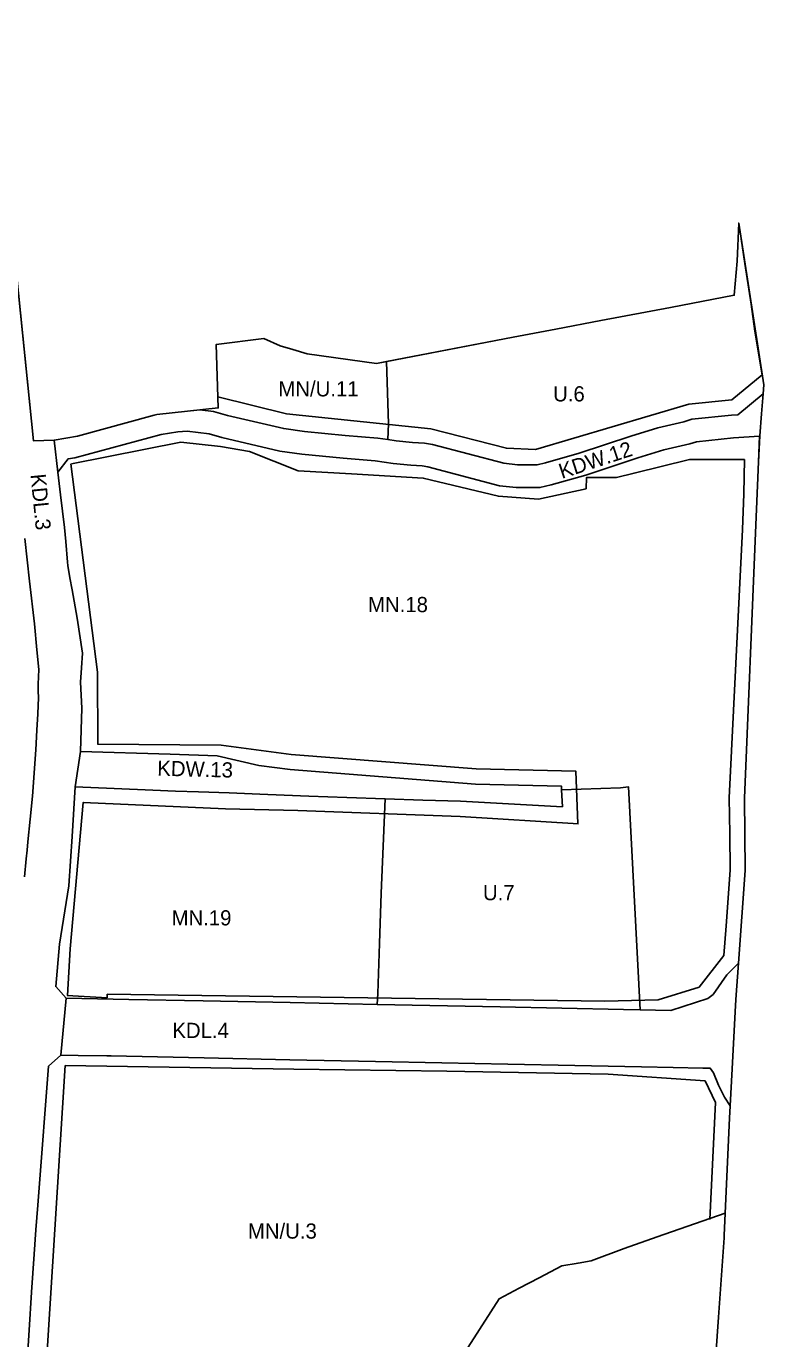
# Model space of a CAD drawing. Extents: x 7423274 to 7424514, y 5542390 to 5544261.
# Drawn here: x 7424240.7 to 7424434.8, y 5543020.6 to 5543366 of the extents above; entities that cross this region are included whole.
import ezdxf

# ---------------------------------------------------------------- set-up
doc = ezdxf.new("R2010")
doc.units = 0
for name, color, linetype in [('granica obszaru objętego planem', 7, 'Continuous'), ('LIN_Granica Planu', 7, 'Continuous'), ('linie rozgraniczające tereny o różnym przeznaczeniu lub różnych zasadach zagospodarowania', 7, 'Continuous'), ('nieprzekraczalna linia zabudowy', 7, 'Continuous'), ('oznaczenia terenów', 7, 'Continuous')]:
    doc.layers.add(name, color=color, linetype=linetype)

msp = doc.modelspace()

# ---------------------------------------------------------------- linework, layer by layer
at = {"layer": 'granica obszaru objętego planem'}
for p, q in [((7424228.51, 5543394.73), (7424242.62, 5543256.86)), ((7424427.77, 5543304.14), (7424428.18, 5543314.14)), ((7424428.18, 5543314.14), (7424434.77, 5543271.57)), ((7424391.88, 5543288.5), (7424410.21, 5543291.99)), ((7424380.04, 5543286.24), (7424391.88, 5543288.5)), ((7424303.2, 5543283.79), (7424307.53, 5543281.87)), ((7424332.88, 5543277.25), (7424368.81, 5543284.1)), ((7424368.81, 5543284.1), (7424380.04, 5543286.24)), ((7424307.53, 5543281.87), (7424310.86, 5543280.86)), ((7424310.86, 5543280.86), (7424314.62, 5543279.75)), ((7424314.62, 5543279.75), (7424332.88, 5543277.25)), ((7424254.14, 5543258.07), (7424274.35, 5543263.58)), ((7424274.35, 5543263.58), (7424275.03, 5543263.77)), ((7424275.03, 5543263.77), (7424291.22, 5543265.54)), ((7424434.16, 5543263.98), (7424433.7, 5543258.21)), ((7424242.62, 5543256.86), (7424248.04, 5543257.08)), ((7424248.04, 5543257.08), (7424254.14, 5543258.07)), ((7424433.7, 5543258.21), (7424433.42, 5543251.38)), ((7424433.42, 5543251.38), (7424432.63, 5543232.65)), ((7424432.63, 5543232.65), (7424429.7, 5543162.87)), ((7424429.7, 5543162.87), (7424429.92, 5543143.78)), ((7424427.46, 5543109.89), (7424427.29, 5543106.64)), ((7424427.29, 5543106.64), (7424426.47, 5543091.66)), ((7424426.47, 5543091.66), (7424425.77, 5543078.62))]:
    msp.add_line(p, q, dxfattribs=at)
for points in [[(7424410.21, 5543291.99), (7424426.99, 5543295.19), (7424427.77, 5543304.14)], [(7424291.22, 5543265.54), (7424290.65, 5543282.2), (7424303.2, 5543283.79)], [(7424434.77, 5543271.57), (7424434.59, 5543269.27), (7424434.16, 5543263.98)], [(7424429.92, 5543143.78), (7424428.16, 5543119.46), (7424427.46, 5543109.89)], [(7424425.77, 5543078.62), (7424424.34, 5543047.76), (7424424.32, 5543047.16)], [(7424424.32, 5543047.16), (7424422.87, 5543026.31), (7424417.89, 5542954.87)]]:
    msp.add_lwpolyline(points, dxfattribs=at)
at = {"layer": 'LIN_Granica Planu'}
for p, q in [((7424242.62, 5543256.86), (7424228.51, 5543394.73)), ((7424428.18, 5543314.14), (7424427.77, 5543304.14)), ((7424434.77, 5543271.57), (7424428.18, 5543314.14)), ((7424410.21, 5543291.99), (7424391.88, 5543288.5)), ((7424391.88, 5543288.5), (7424380.04, 5543286.24)), ((7424307.53, 5543281.87), (7424303.2, 5543283.79)), ((7424368.81, 5543284.1), (7424332.88, 5543277.25)), ((7424380.04, 5543286.24), (7424368.81, 5543284.1)), ((7424310.86, 5543280.86), (7424307.53, 5543281.87)), ((7424314.62, 5543279.75), (7424310.86, 5543280.86)), ((7424332.88, 5543277.25), (7424314.62, 5543279.75)), ((7424274.35, 5543263.58), (7424254.14, 5543258.07)), ((7424275.03, 5543263.77), (7424274.35, 5543263.58)), ((7424291.22, 5543265.54), (7424275.03, 5543263.77)), ((7424433.7, 5543258.21), (7424434.16, 5543263.98)), ((7424248.04, 5543257.08), (7424242.62, 5543256.86)), ((7424254.14, 5543258.07), (7424248.04, 5543257.08)), ((7424433.42, 5543251.38), (7424433.7, 5543258.21)), ((7424432.63, 5543232.65), (7424433.42, 5543251.38)), ((7424429.7, 5543162.87), (7424432.63, 5543232.65)), ((7424429.92, 5543143.78), (7424429.7, 5543162.87)), ((7424427.29, 5543106.64), (7424427.46, 5543109.89)), ((7424426.47, 5543091.66), (7424427.29, 5543106.64)), ((7424425.77, 5543078.62), (7424426.47, 5543091.66))]:
    msp.add_line(p, q, dxfattribs=at)
for points in [[(7424427.77, 5543304.14), (7424426.99, 5543295.19), (7424410.21, 5543291.99)], [(7424303.2, 5543283.79), (7424290.65, 5543282.2), (7424291.22, 5543265.54)], [(7424434.16, 5543263.98), (7424434.59, 5543269.27), (7424434.77, 5543271.57)], [(7424427.46, 5543109.89), (7424428.16, 5543119.46), (7424429.92, 5543143.78)], [(7424424.32, 5543047.16), (7424424.34, 5543047.76), (7424425.77, 5543078.62)], [(7424417.89, 5542954.87), (7424422.87, 5543026.31), (7424424.32, 5543047.16)]]:
    msp.add_lwpolyline(points, dxfattribs=at)
at = {"layer": 'linie rozgraniczające tereny o różnym przeznaczeniu lub różnych zasadach zagospodarowania'}
for points in [[(7424129.39, 5544001.9), (7424129.8, 5543999.91), (7424131.7, 5543990.87), (7424133.97, 5543980.01), (7424148.11, 5543912.49), (7424163.08, 5543838.56), (7424169.46, 5543807.01), (7424175.57, 5543776.81), (7424186.15, 5543728.82), (7424192.74, 5543698.89), (7424202.07, 5543636.25), (7424204.36, 5543612.15), (7424228.15, 5543398.17), (7424228.51, 5543394.73), (7424242.62, 5543256.86), (7424248.04, 5543257.08)], [(7424335.49, 5543277.75), (7424368.81, 5543284.1), (7424380.04, 5543286.24), (7424391.88, 5543288.5), (7424410.21, 5543291.99), (7424426.99, 5543295.19), (7424427.77, 5543304.14), (7424428.18, 5543314.14), (7424434.77, 5543271.57), (7424434.59, 5543269.27)], [(7424286.39, 5543265.01), (7424291.22, 5543265.54), (7424290.65, 5543282.2), (7424303.2, 5543283.79), (7424307.53, 5543281.87), (7424310.86, 5543280.86), (7424314.62, 5543279.75), (7424332.88, 5543277.25), (7424335.49, 5543277.75)], [(7424335.83, 5543257.19), (7424336.04, 5543261.36), (7424335.49, 5543277.75)], [(7424434.59, 5543269.27), (7424427.91, 5543263.71), (7424426.31, 5543263.61), (7424415.85, 5543262.54), (7424413.72, 5543261.89), (7424406.88, 5543260.3), (7424399.81, 5543258.07), (7424386.17, 5543253.6), (7424377.29, 5543251.06), (7424375.16, 5543250.56), (7424369.96, 5543250.56), (7424366.33, 5543250.98), (7424347.58, 5543255.93), (7424345.47, 5543256.26), (7424342.33, 5543256.43), (7424338.01, 5543256.85), (7424335.83, 5543257.19)], [(7424434.59, 5543269.27), (7424434.16, 5543263.98), (7424433.7, 5543258.21), (7424433.69, 5543258.07)], [(7424248.04, 5543257.08), (7424254.14, 5543258.07), (7424274.35, 5543263.58), (7424275.03, 5543263.77), (7424286.39, 5543265.01)], [(7424335.83, 5543257.19), (7424333.25, 5543257.6), (7424324.65, 5543258.3), (7424313.9, 5543259.33), (7424308.46, 5543260.07), (7424293.69, 5543263.5), (7424289.99, 5543264.57), (7424286.39, 5543265.01)], [(7424249, 5543248.64), (7424248.04, 5543257.08)], [(7424249, 5543248.64), (7424251.69, 5543252.13), (7424253.46, 5543252.4), (7424276.22, 5543258.56), (7424280.57, 5543259.24), (7424283.02, 5543259.38), (7424288.79, 5543258.67), (7424292.18, 5543257.7), (7424307.38, 5543254.16), (7424313.21, 5543253.37), (7424324.12, 5543252.32), (7424332.54, 5543251.64), (7424337.25, 5543250.89), (7424341.88, 5543250.44), (7424344.85, 5543250.28), (7424346.35, 5543250.05), (7424365.2, 5543245.07), (7424369.61, 5543244.56), (7424375.87, 5543244.56), (7424378.81, 5543245.26), (7424387.93, 5543247.86), (7424401.65, 5543252.36), (7424408.46, 5543254.51), (7424415.28, 5543256.09), (7424417.04, 5543256.63), (7424426.81, 5543257.63), (7424433.69, 5543258.07)], [(7424433.69, 5543258.07), (7424433.42, 5543251.38), (7424432.63, 5543232.65), (7424429.7, 5543162.87), (7424429.92, 5543143.78), (7424428.16, 5543119.46)], [(7424255, 5543175.12), (7424255.14, 5543180.83), (7424255.28, 5543186.53), (7424254.96, 5543193.39), (7424255.21, 5543197.17), (7424255.46, 5543200.96), (7424254.1, 5543210.18), (7424252.75, 5543217.65), (7424252.17, 5543220.84), (7424251.59, 5543224.04), (7424251.52, 5543224.96), (7424251.08, 5543230.36), (7424250.76, 5543234.08), (7424249.66, 5543242.66), (7424249, 5543248.64)], [(7424240.23, 5543142.11), (7424240.7, 5543146.91), (7424240.92, 5543149.15), (7424241.14, 5543151.39), (7424241.72, 5543157.36), (7424242.3, 5543163.33), (7424243.25, 5543175.52), (7424243.51, 5543180.74), (7424243.7, 5543185.01), (7424243.89, 5543189.29), (7424243.83, 5543191.04), (7424243.78, 5543192.8), (7424243.88, 5543194.74), (7424243.99, 5543196.67), (7424243.5, 5543201.86), (7424242.88, 5543208.75), (7424241.58, 5543219.98), (7424240.28, 5543231.21)], [(7424253.6, 5543165.85), (7424254.3, 5543170.49), (7424255, 5543175.12)], [(7424381.58, 5543165.08), (7424381.54, 5543166.03), (7424358.88, 5543166.55), (7424310.11, 5543170.35), (7424301.93, 5543171.45), (7424290.94, 5543173.98), (7424278.52, 5543174.39), (7424255, 5543175.12)], [(7424251.2, 5543110.23), (7424251.18, 5543110.24), (7424248.45, 5543113.28), (7424249.44, 5543124.46), (7424251.89, 5543139.74), (7424252.75, 5543152.79), (7424253.6, 5543165.85)], [(7424253.6, 5543165.85), (7424263.79, 5543165.4), (7424273.98, 5543164.94), (7424279.99, 5543164.71), (7424285.99, 5543164.47), (7424294.06, 5543164.21), (7424302.13, 5543163.94), (7424308.58, 5543163.67), (7424315.04, 5543163.39), (7424325.07, 5543163.01), (7424335.1, 5543162.64)], [(7424335.1, 5543162.64), (7424345.04, 5543162.33), (7424354.98, 5543162.02), (7424381.8, 5543160.57), (7424381.58, 5543165.08)], [(7424381.58, 5543165.08), (7424397.1, 5543165.55), (7424399.2, 5543165.79), (7424402.26, 5543107.18)], [(7424333.02, 5543108.57), (7424333.22, 5543111.42), (7424333.65, 5543124.62), (7424334.08, 5543137.82), (7424334.59, 5543150.23), (7424335.1, 5543162.64)], [(7424402.26, 5543107.18), (7424406.29, 5543107.09), (7424410.32, 5543107), (7424420.07, 5543110.12), (7424421.48, 5543111.19), (7424425.04, 5543116.4), (7424428.16, 5543119.46)], [(7424428.16, 5543119.46), (7424427.46, 5543109.89), (7424427.29, 5543106.64), (7424426.47, 5543091.66), (7424425.95, 5543081.92)], [(7424249.76, 5543095.26), (7424251.2, 5543110.23)], [(7424251.2, 5543110.23), (7424267.7, 5543109.9), (7424287.21, 5543109.5), (7424310.12, 5543109.04), (7424333.02, 5543108.57)], [(7424333.02, 5543108.57), (7424365.44, 5543107.91), (7424397.86, 5543107.25), (7424402.26, 5543107.18)], [(7424249.76, 5543095.26), (7424246.58, 5543092.32), (7424246.18, 5543087.73), (7424245.57, 5543079.75), (7424244.96, 5543071.76), (7424244.34, 5543063.74), (7424243.73, 5543055.72), (7424243.24, 5543049.29), (7424242.76, 5543042.86), (7424242.08, 5543032.87), (7424241.41, 5543022.87), (7424241.09, 5543017.38)], [(7424249.76, 5543095.26), (7424254.37, 5543095.17), (7424261.89, 5543095.02), (7424263.01, 5543095.01), (7424275.24, 5543094.75), (7424287.47, 5543094.49), (7424310.04, 5543094.04), (7424332.62, 5543093.58), (7424350.03, 5543093.23), (7424367.43, 5543092.87), (7424385.02, 5543092.51), (7424402.6, 5543092.16), (7424410.97, 5543091.98), (7424418.72, 5543091.82), (7424420.7, 5543091.77), (7424421.53, 5543090.59), (7424422.9, 5543087.3), (7424424.45, 5543084.21), (7424425.95, 5543081.92)], [(7424418.72, 5543091.82), (7424418.72, 5543091.82)], [(7424425.95, 5543081.92), (7424425.77, 5543078.62), (7424424.61, 5543053.66)], [(7424424.61, 5543053.66), (7424406.68, 5543047.4), (7424398.02, 5543044.37), (7424389.32, 5543041.09), (7424385.91, 5543040.52), (7424381.64, 5543039.8), (7424378.65, 5543038.23), (7424375.65, 5543036.66), (7424370.41, 5543033.9), (7424365.16, 5543031.13), (7424357.78, 5543019.66), (7424350.4, 5543008.19), (7424346.34, 5543001.91), (7424336.37, 5542996.95), (7424330.1, 5542993.79), (7424325.93, 5542993.21), (7424321.76, 5542992.64), (7424321.57, 5542991.31), (7424311.17, 5542989.4), (7424310.33, 5542981.17), (7424309.93, 5542977.57), (7424308.66, 5542968.35), (7424308.41, 5542964.37), (7424299.6, 5542953.02)], [(7424424.61, 5543053.66), (7424424.34, 5543047.76), (7424424.32, 5543047.16), (7424422.87, 5543026.31), (7424417.89, 5542954.87)]]:
    msp.add_lwpolyline(points, dxfattribs=at)
at = {"layer": 'nieprzekraczalna linia zabudowy'}
for p, q in [((7424392.94, 5543109.42), (7424406.94, 5543109.79)), ((7424422.03, 5543082.8), (7424419.38, 5543088.49)), ((7424420.54, 5543052.03), (7424422.03, 5543082.8))]:
    msp.add_line(p, q, dxfattribs=at)
for points in [[(7424434.35, 5543274.25), (7424434.35, 5543274.25), (7424432.43, 5543285.72), (7424431.48, 5543292.86), (7424429.83, 5543303.5), (7424428.82, 5543310.03)], [(7424291.12, 5543268.4), (7424309.19, 5543264.01), (7424347.14, 5543260.05), (7424367.07, 5543254.92), (7424374.69, 5543254.56), (7424415.05, 5543266.48), (7424426.35, 5543267.62), (7424434.35, 5543274.25)], [(7424291.84, 5543255.4), (7424281.36, 5543256.5), (7424252.63, 5543250.84)], [(7424326.31, 5543248.22), (7424312.27, 5543248.98), (7424299.42, 5543254.03), (7424291.84, 5543255.4), (7424291.84, 5543255.4)], [(7424252.46, 5543250.82), (7424259.42, 5543196.01), (7424259.51, 5543177.02)], [(7424429.67, 5543251.98), (7424415.25, 5543251.97), (7424400.64, 5543248.4), (7424396.03, 5543247.21)], [(7424424.3, 5543121.49), (7424424.86, 5543129.24), (7424425.92, 5543143.9), (7424425.81, 5543153.42), (7424425.7, 5543162.93), (7424427.43, 5543198.25), (7424429.16, 5543233.56), (7424429.55, 5543242.93), (7424429.67, 5543251.98)], [(7424388.06, 5543244.27), (7424375.48, 5543241.54), (7424364.94, 5543242.27), (7424345.15, 5543247.07), (7424326.31, 5543248.22)], [(7424396.03, 5543247.21), (7424388.15, 5543247.23), (7424388.06, 5543244.27)], [(7424259.48, 5543177.02), (7424291.99, 5543176.81), (7424310.43, 5543174.34)], [(7424310.43, 5543174.34), (7424359.08, 5543170.55), (7424385.35, 5543169.95), (7424385.82, 5543156.13)], [(7424255.69, 5543161.71), (7424255.69, 5543161.71), (7424252.2, 5543123.23), (7424251.51, 5543110.94)], [(7424354.86, 5543158.02), (7424312.18, 5543159.59), (7424293.08, 5543160.04), (7424255.69, 5543161.71)], [(7424386, 5543156.12), (7424354.86, 5543158.02)], [(7424406.94, 5543109.79), (7424417.77, 5543113.1), (7424424.3, 5543121.49)], [(7424251.49, 5543110.95), (7424261.97, 5543110.34), (7424262.02, 5543111.25)], [(7424262.01, 5543111.26), (7424392.94, 5543109.42)], [(7424250.95, 5543092.55), (7424243.55, 5542975.58), (7424243.55, 5542975.58), (7424243.55, 5542975.58), (7424243.55, 5542975.58), (7424249.6, 5542931.07)], [(7424419.38, 5543088.49), (7424393.86, 5543090.2), (7424351.37, 5543091.01), (7424311.11, 5543091.54), (7424250.95, 5543092.55)]]:
    msp.add_lwpolyline(points, dxfattribs=at)

# ---------------------------------------------------------------- texts
at = {"layer": 'oznaczenia terenów'}
for s, p in [('MN/U.11', (7424307.04, 5543268.55)), ('U.6', (7424379.34, 5543267.23)), ('MN.18', (7424330.64, 5543211.79)), ('U.7', (7424360.88, 5543135.98)), ('MN.19', (7424278.93, 5543129.36)), ('KDL.4', (7424279.14, 5543099.74)), ('MN/U.3', (7424299.02, 5543046.95))]:
    msp.add_text(s, height=4, dxfattribs=at).set_placement(p)
for s, rotation, p in [('KDW.12', 18.2244, (7424381.63, 5543246.82)), ('KDL.3', 275.5492, (7424241.8, 5543248)), ('KDW.13', 358.527, (7424275.13, 5543168.76))]:
    msp.add_text(s, height=4, rotation=rotation, dxfattribs=at).set_placement(p)

doc.saveas('drawing.dxf')
